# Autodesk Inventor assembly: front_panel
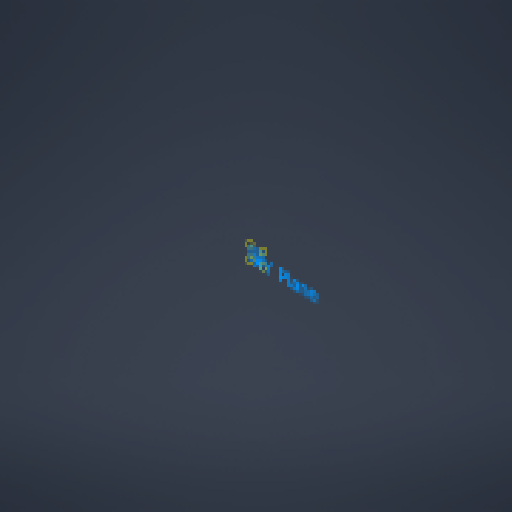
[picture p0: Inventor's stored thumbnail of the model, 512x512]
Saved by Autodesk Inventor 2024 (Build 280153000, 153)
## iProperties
Created: 2023-09
Part Number: front_panel
Document SubType Name: Assembly
Designer: mammothbane
Author: mammothbane
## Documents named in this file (3)
- \\caemlyn.p.hs.npry.dev\media\modeling\mit\mas.863\front_panel.iam
- \\caemlyn.p.hs.npry.dev\media\modeling\mit\mas.863\mounting_panel.ipt
- \\caemlyn.p.hs.npry.dev\media\modeling\mit\mas.863\mfd.ipt
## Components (4 placed, 2 different names)
1. mounting_panel:1 — Planar:2, Planar:3, Planar:4
2. mfd:1 — Planar:3
3. mfd:2 — Planar:2
4. mfd:3 — Planar:4
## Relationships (3: PlanarJoint 3)
- Planar:2: mounting_panel:1 ↔ mfd:2
- Planar:3: mounting_panel:1 ↔ mfd:1
- Planar:4: mounting_panel:1 ↔ mfd:3
